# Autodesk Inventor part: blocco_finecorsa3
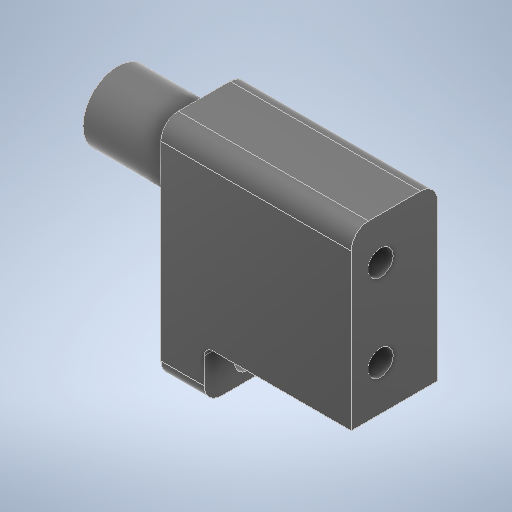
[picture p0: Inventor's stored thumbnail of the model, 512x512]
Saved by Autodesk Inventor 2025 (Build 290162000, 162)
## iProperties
Created: 2026-03
Part Number: blocco_finecorsa3
Material: Generico
Document SubType Name: Modeling
Designer: Ryzen5700u
Density: 1 g/cm^3
Appearance: Liscia - Nero
Author: Ryzen5700u
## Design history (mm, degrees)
sketch "Schizzo1"
  geometry: L1 (10, 5)-(-10, 5); L2 (-10, 5)-(-10, -5); L3 (-10, -5)-(10, -5); L4 (10, -5)-(10, 5); L5 (10, 5)-(-10, -5); L6 (-10, 5)-(10, -5); 1 further point
  constraints: 12 end point, 2 midpoint, 2 parallel, 1 horizontal, 1 perpendicular
  dimensions: "d0" = 20 distance of L3.end L2.end; "d1" = 10 distance of L2.end L1.end
extrude "Estrusione1" new body sketch "Schizzo1" distance "d2" = 22; taper "d3" = 0 deg
sketch "Schizzo2"
  geometry: C1 r 4 at (0, 4); 1 further point
  constraints: 1 centre point
  dimensions: "d4" = 8 diameter of C1; "d5" = 4 distance of point (0, 0) C1.centre
extrude "Estrusione2" join sketch "Schizzo2" distance "d6" = 10; taper "d7" = 0 deg
sketch "Schizzo3"
  geometry: C1 r 1.25 at (-1.6, 5.125) reference; C2 r 1.25 at (-1.6, -4.875) reference; 1 further point
hole "Foro1" sketch "Schizzo3" at (-1.6, 5.125), (-1.6, -4.875) diameter "d9" = 2.9; stored, may be unused: countersink angle "d13" = 90 deg, drill point angle "d15" = 118 deg; dims "d10" = 6, "d11" = 5.5, "d12" = 2.9, "d14" = 8
sketch "Schizzo4"
  geometry: L1 (5, -10)-(-5, -10) reference; L2 (5, 10)-(5, -10) reference; L3 (-5, 10)-(5, 10) reference; L4 (-5, -10)-(-5, 10) reference; L5 (5, -10)-(-5, -10) reference; L6 (5, -10)-(-5, -10); L7 (-5, -10)-(-5, -16); L8 (-5, -16)-(5, -16); L9 (5, -16)-(5, -10); C1 r 4 at (0, 4) reference; 2 further points
  constraints: 8 end point, 2 parallel, 1 horizontal, 1 perpendicular
  dimensions: "d16" = 6 distance of L7.end L6.end
extrude "Estrusione3" join sketch "Schizzo4" distance "d17" = 5; taper "d18" = 0 deg
fillet "Raccordo2" dims "d19" = 1
sketch "Schizzo5"
  geometry: L1 (-5, -16)-(5, -16) reference; 2 further points
  dimensions: "d27" = 2.5 distance from line of L1 point (0, -13.5)
hole "Foro2" sketch "Schizzo5" at (0, -13.5) diameter "d20" = 2.9; stored, may be unused: countersink angle "d24" = 90 deg, drill point angle "d26" = 118 deg; dims "d21" = 6, "d22" = 4, "d23" = 2, "d25" = 8
fillet "Raccordo3" dims "d28" = 2
node "Solido1"
node "Riferimento1"
node "Riferimento2"
node "Linea chiusa proiettata1"
